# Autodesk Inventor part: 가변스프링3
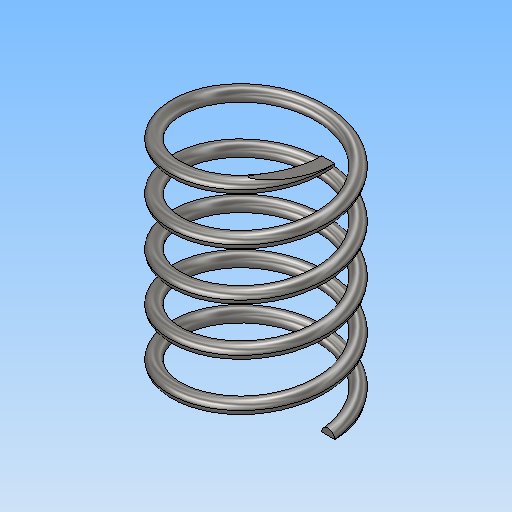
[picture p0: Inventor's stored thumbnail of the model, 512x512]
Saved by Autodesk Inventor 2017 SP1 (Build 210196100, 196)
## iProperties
Part Number: 가변스프링3
Material: 강철, 연강
Document SubType Name: Modeling
Designer: MRC
Density: 7.85 g/cm^3
Appearance: 반연마
Mass: 8.42324 g
Surface Area: 21.7217 cm^2
Volume: 1.07302 cm^3
Author: MRC
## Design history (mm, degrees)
sketch "스케치1"
  geometry: L1 (0, 0)-(0, 36.411); L2 (0, 36.411)-(11, 36.411); L3 (0, 0)-(11, 0); C1 r 1 at (11, 0)
  constraints: 6 end point, 2 horizontal, 1 centre point, 1 coincident, 1 vertical
  dimensions: "d0" = 36.4112 distance of L1.start L1.end (derived); "d1" = 11 distance of L1.end L2.end; "d2" = 22 diameter of L3.end L1; "d3" = 2 diameter of C1
feature "코일1" sketch "스케치1" pitch "d4" = 10; turns "d6" = 5; dims "d5" = 36.4112 (= d0), "d7" = 0, angle "d8" = 90 deg, angle "d9" = 90 deg, "d10" = 0, "d11" = 0
sketch "스케치2"
  geometry: L1 (36.411, 20)-(0, 20); L2 (0, 20)-(0, -20); L3 (0, -20)-(36.411, -20); L4 (36.411, -20)-(36.411, 20); 2 further points
  constraints: 8 end point, 2 parallel, 1 coincident, 1 horizontal, 1 midpoint, 1 perpendicular
  dimensions: "d12" = 36.4112 distance of L2.end L3.end (= d0); "d13" = 40 distance of L3.end L1.start
extrude "돌출1" sketch "스케치2" stored distance "d14" = 0; taper "d15" = 0 deg
node "솔리드1"
